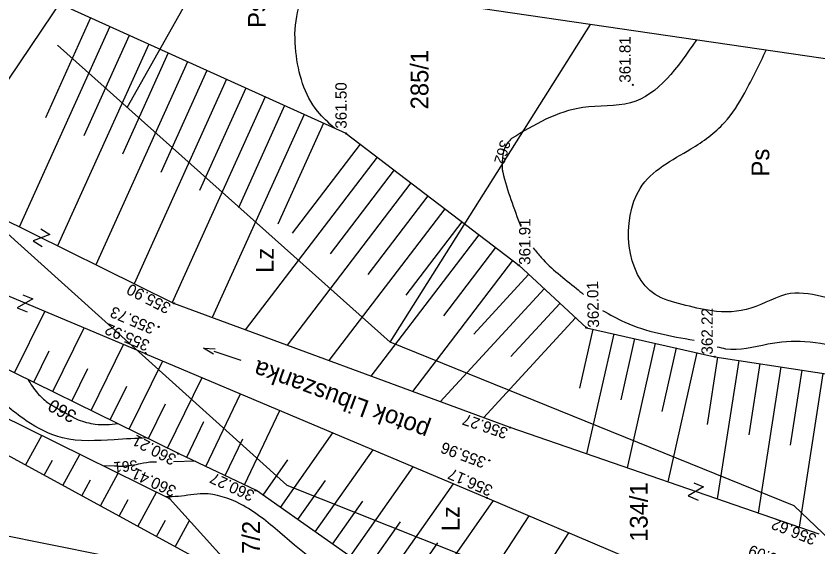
# Model space of a CAD drawing. Extents: x 4635329 to 4651863, y 5356628 to 5367582.
# Drawn here: x 4651136.6 to 4651193.1, y 5356715.5 to 5356752.8 of the extents above; entities that cross this region are included whole.
import ezdxf

# ---------------------------------------------------------------- set-up
doc = ezdxf.new("R2010")
doc.units = 0
for name, color, linetype in [('Level 1', 7, 'Continuous'), ('Level 12', 7, 'Continuous'), ('Level 4', 7, 'Continuous'), ('Level 44', 7, 'Continuous'), ('Level 45', 7, 'Continuous'), ('Level 46', 7, 'Continuous'), ('Level 47', 7, 'Continuous'), ('Level 48', 7, 'Continuous'), ('Level 5', 7, 'Continuous'), ('Level 50', 7, 'Continuous'), ('Level 51', 7, 'Continuous'), ('Level 53', 7, 'Continuous')]:
    doc.layers.add(name, color=color, linetype=linetype)

msp = doc.modelspace()

# ---------------------------------------------------------------- linework, layer by layer
at = {"layer": 'Level 1'}
for p, q in [((4651142.124, 5356757.357), (4651130.91, 5356740.759)), ((4651210.82, 5356747.317), (4651142.124, 5356757.357))]:
    msp.add_line(p, q, dxfattribs=at)
at = {"layer": 'Level 4'}
for p, q in [((4651144.438, 5356746.409), (4651149.95, 5356756.213)), ((4651162.95, 5356729.899), (4651177.067, 5356752.25)), ((4651162.95, 5356729.899), (4651139.533, 5356750.784)), ((4651133.66, 5356739.652), (4651155.671, 5356719.834)), ((4651191.397, 5356718.379), (4651162.95, 5356729.899)), ((4651155.671, 5356719.834), (4651189.548, 5356706.371)), ((4651208.259, 5356702.31), (4651191.397, 5356718.379)), ((4651130.975, 5356717.257), (4651177.535, 5356707.977))]:
    msp.add_line(p, q, dxfattribs=at)
at = {"layer": 'Level 44'}
for centre in [(4651180.045, 5356747.997), (4651159.865, 5356744.577), (4651172.015, 5356735.297), (4651147.735, 5356732.617), (4651146.655, 5356730.967), (4651176.775, 5356730.907), (4651145.732, 5356729.122), (4651185.825, 5356728.867), (4651171.415, 5356723.877), (4651148.045, 5356722.037), (4651169.945, 5356721.567), (4651153.475, 5356719.457), (4651147.415, 5356718.887), (4651169.765, 5356718.937)]:
    msp.add_circle(centre, 0.04, dxfattribs=at)
at = {"layer": 'Level 46'}
for p, q in [((4651143.548, 5356721.165), (4651142.743, 5356721.189)), ((4651149.228, 5356721.503), (4651147.711, 5356721.476))]:
    msp.add_line(p, q, dxfattribs=at)
for points in [[(4651159.027, 5356744.956), (4651157.839, 5356746.143), (4651156.321, 5356750.33), (4651156.382, 5356752.818), (4651156.989, 5356755.003), (4651157.028, 5356755.179)], [(4651184.527, 5356751.16), (4651179.887, 5356746.733), (4651176.521, 5356746.4), (4651171.498, 5356744.217)], [(4651204.195, 5356724.252), (4651203.361, 5356725.098), (4651200.995, 5356727.826), (4651199.873, 5356729.585), (4651196.249, 5356732.275), (4651193.641, 5356733.033), (4651191.154, 5356733.306), (4651188.364, 5356732.275), (4651185.605, 5356732.093), (4651183.512, 5356732.548), (4651181.615, 5356733.242), (4651180.554, 5356740.7), (4651184.132, 5356743.489), (4651186.498, 5356745.338), (4651187.923, 5356747.43), (4651189.44, 5356750.442)], [(4651171.498, 5356744.217), (4651171.224, 5356743.914), (4651170.834, 5356742.096)], [(4651170.834, 5356742.096), (4651170.89, 5356741.853), (4651172.151, 5356738.034)], [(4651173.04, 5356736.531), (4651173.589, 5356735.85), (4651176.076, 5356733.667), (4651176.575, 5356733.245)], [(4651177.917, 5356732.125), (4651179.472, 5356731.302), (4651184.374, 5356730.029)], [(4651185.981, 5356729.569), (4651186.583, 5356729.429), (4651189.555, 5356729.762), (4651192.163, 5356729.944), (4651195.087, 5356729.339), (4651196.815, 5356728.581), (4651198.605, 5356727.096), (4651198.829, 5356726.859)], [(4651145.844, 5356723.147), (4651143.522, 5356723.027), (4651139.883, 5356723.148), (4651137.335, 5356724.361), (4651134.727, 5356726.726), (4651133.575, 5356728.423), (4651132.919, 5356729.492)], [(4651137.437, 5356727.274), (4651138.124, 5356726.301), (4651138.83, 5356725.636)], [(4651138.83, 5356725.636), (4651139.883, 5356725.028), (4651140.991, 5356724.421)], [(4651140.991, 5356724.421), (4651142.188, 5356724.118), (4651143.787, 5356724.157)], [(4651145.374, 5356721.327), (4651144.128, 5356721.147), (4651143.548, 5356721.165)], [(4651146.499, 5356721.455), (4651146.251, 5356721.451), (4651145.374, 5356721.327)], [(4651163.601, 5356712.367), (4651161.083, 5356712.669), (4651155.2, 5356716.489), (4651152.41, 5356718.49), (4651149.802, 5356719.218), (4651148.043, 5356719.036), (4651147.174, 5356719.006)]]:
    msp.add_spline(points, degree=3, dxfattribs=at)
at = {"layer": 'Level 48'}
for p, q in [((4651141.854, 5356752.714), (4651138.676, 5356745.681)), ((4651143.221, 5356752.097), (4651136.845, 5356737.985)), ((4651144.588, 5356751.479), (4651141.39, 5356744.4)), ((4651145.955, 5356750.862), (4651139.538, 5356736.658)), ((4651147.322, 5356750.244), (4651144.103, 5356743.119)), ((4651148.689, 5356749.626), (4651142.23, 5356735.331)), ((4651150.056, 5356749.009), (4651146.816, 5356741.838)), ((4651151.423, 5356748.391), (4651144.922, 5356734.004)), ((4651152.79, 5356747.774), (4651149.529, 5356740.557)), ((4651154.157, 5356747.156), (4651147.615, 5356732.677)), ((4651155.524, 5356746.538), (4651152.272, 5356739.341)), ((4651156.891, 5356745.921), (4651150.43, 5356731.622)), ((4651158.257, 5356745.303), (4651155.049, 5356738.202)), ((4651160.847, 5356743.827), (4651156.066, 5356737.567)), ((4651162.039, 5356742.916), (4651152.757, 5356730.763)), ((4651163.231, 5356742.006), (4651158.73, 5356736.113)), ((4651164.423, 5356741.095), (4651155.702, 5356729.676)), ((4651165.616, 5356740.185), (4651161.395, 5356734.659)), ((4651166.808, 5356739.274), (4651158.647, 5356728.59)), ((4651168, 5356738.364), (4651164.059, 5356733.205)), ((4651169.192, 5356737.453), (4651161.592, 5356727.503)), ((4651170.384, 5356736.543), (4651166.724, 5356731.751)), ((4651171.576, 5356735.632), (4651164.536, 5356726.416)), ((4651172.711, 5356734.655), (4651168.839, 5356730.456)), ((4651173.814, 5356733.638), (4651166.489, 5356725.695)), ((4651174.917, 5356732.621), (4651171.464, 5356728.877)), ((4651136.512, 5356727.728), (4651138.637, 5356732.057)), ((4651176.019, 5356731.604), (4651169.534, 5356724.572)), ((4651139.205, 5356726.406), (4651141.408, 5356730.895)), ((4651177.236, 5356730.803), (4651176.302, 5356726.66)), ((4651178.699, 5356730.473), (4651176.795, 5356722.025)), ((4651141.898, 5356725.084), (4651144.179, 5356729.733)), ((4651180.162, 5356730.143), (4651179.192, 5356725.839)), ((4651181.625, 5356729.814), (4651179.648, 5356721.043)), ((4651137.858, 5356727.067), (4651138.94, 5356729.272)), ((4651183.089, 5356729.484), (4651182.082, 5356725.018)), ((4651184.552, 5356729.154), (4651182.502, 5356720.061)), ((4651144.591, 5356723.762), (4651146.95, 5356728.568)), ((4651186.018, 5356728.837), (4651185.286, 5356724.096)), ((4651187.5, 5356728.608), (4651185.995, 5356718.859)), ((4651140.551, 5356725.745), (4651141.672, 5356728.03)), ((4651188.983, 5356728.379), (4651188.209, 5356723.371)), ((4651190.465, 5356728.151), (4651188.877, 5356717.866)), ((4651191.948, 5356727.922), (4651191.133, 5356722.646)), ((4651147.283, 5356722.44), (4651149.718, 5356727.399)), ((4651193.43, 5356727.693), (4651191.76, 5356716.874)), ((4651143.244, 5356724.423), (4651144.405, 5356726.787)), ((4651149.988, 5356721.142), (4651152.419, 5356726.259)), ((4651145.937, 5356723.101), (4651147.135, 5356725.542)), ((4651152.698, 5356719.855), (4651155.186, 5356725.091)), ((4651148.633, 5356721.786), (4651149.835, 5356724.314)), ((4651155.23, 5356718.263), (4651158.927, 5356723.512)), ((4651137.285, 5356721.239), (4651138.42, 5356723.32)), ((4651151.343, 5356720.499), (4651152.573, 5356723.087)), ((4651157.682, 5356716.536), (4651161.755, 5356722.318)), ((4651139.918, 5356719.802), (4651141.113, 5356721.992)), ((4651138.601, 5356720.521), (4651139.184, 5356721.588)), ((4651154.004, 5356719.127), (4651155.758, 5356721.618)), ((4651142.551, 5356718.365), (4651143.806, 5356720.665)), ((4651160.135, 5356714.808), (4651164.584, 5356721.124)), ((4651141.235, 5356719.084), (4651141.847, 5356720.206)), ((4651156.456, 5356717.399), (4651158.399, 5356720.157)), ((4651162.588, 5356713.08), (4651167.412, 5356719.93)), ((4651145.185, 5356716.928), (4651146.5, 5356719.338)), ((4651143.868, 5356717.647), (4651144.511, 5356718.824)), ((4651158.909, 5356715.672), (4651161.039, 5356718.696)), ((4651165.04, 5356711.353), (4651170.24, 5356718.735)), ((4651146.501, 5356716.21), (4651147.129, 5356717.36)), ((4651147.818, 5356715.491), (4651148.822, 5356717.331)), ((4651161.361, 5356713.944), (4651163.68, 5356717.236)), ((4651167.549, 5356709.708), (4651172.743, 5356717.671)), ((4651170.062, 5356708.069), (4651175.548, 5356716.48)), ((4651163.814, 5356712.217), (4651166.32, 5356715.775))]:
    msp.add_line(p, q, dxfattribs=at)
for points in [[(4651159.865, 5356744.577), (4651140.487, 5356753.332)], [(4651159.865, 5356744.577), (4651172.015, 5356735.297), (4651176.775, 5356730.907), (4651185.825, 5356728.867), (4651199.945, 5356726.687), (4651204.495, 5356722.447), (4651214.585, 5356716.447), (4651220.475, 5356711.587), (4651225.965, 5356710.777), (4651235.295, 5356710.407), (4651240.045, 5356721.267)], [(4651181.945, 5356698.957), (4651174.695, 5356705.047), (4651165.205, 5356711.237), (4651153.535, 5356719.457), (4651148.105, 5356722.037), (4651132.135, 5356729.877)], [(4651129.435, 5356727.747), (4651147.415, 5356718.887), (4651153.085, 5356712.617)], [(4651153.085, 5356712.617), (4651128.035, 5356726.287)]]:
    msp.add_lwpolyline(points, dxfattribs=at)
at = {"layer": 'Level 50'}
for p, q in [((4651147.735, 5356732.617), (4651134.798, 5356738.994)), ((4651145.685, 5356729.101), (4651133.346, 5356734.276)), ((4651171.415, 5356723.877), (4651147.735, 5356732.617)), ((4651145.685, 5356729.101), (4651169.765, 5356718.937)), ((4651150.508, 5356729.036), (4651149.81, 5356729.476)), ((4651149.81, 5356729.476), (4651150.633, 5356729.416)), ((4651152.47, 5356728.601), (4651150.57, 5356729.226)), ((4651193.175, 5356716.387), (4651171.415, 5356723.877)), ((4651169.765, 5356718.937), (4651190.495, 5356710.127))]:
    msp.add_line(p, q, dxfattribs=at)
at = {"layer": 'Level 53'}
for p, q in [((4651138.355, 5356737.859), (4651138.987, 5356737.456)), ((4651138.987, 5356737.456), (4651137.817, 5356737.016)), ((4651137.817, 5356737.016), (4651138.45, 5356736.612)), ((4651137.097, 5356733.228), (4651137.786, 5356732.932)), ((4651137.786, 5356732.932), (4651136.703, 5356732.308)), ((4651136.703, 5356732.308), (4651137.392, 5356732.013)), ((4651185.027, 5356719.706), (4651183.954, 5356719.066)), ((4651184.334, 5356719.991), (4651185.027, 5356719.706)), ((4651183.954, 5356719.066), (4651184.647, 5356718.781))]:
    msp.add_line(p, q, dxfattribs=at)

# ---------------------------------------------------------------- texts
at = {"layer": 'Level 12'}
for s, p in [('Ps', (4651154.194, 5356752.007)), ('Ps', (4651189.654, 5356741.551)), ('Lz', (4651154.754, 5356734.76)), ('Lz', (4651167.846, 5356716.584))]:
    msp.add_text(s, height=1.25, rotation=90, dxfattribs=at).set_placement(p)
at = {"layer": 'Level 45'}
for s, rotation, p in [('361.81', 90, (4651179.895, 5356748.147)), ('361.50', 90, (4651159.896, 5356744.909)), ('361.91', 90, (4651172.834, 5356735.326)), ('362.01', 91.3333, (4651177.674, 5356730.919)), ('355.90', 152.9225, (4651147.592, 5356732.551)), ('355.73', 156.9868, (4651146.478, 5356731.151)), ('362.22', 90, (4651185.675, 5356729.017)), ('355.92', 156.9868, (4651146.099, 5356729.956)), ('356.27', 161.0996, (4651171.323, 5356723.804)), ('360.21', 152.4904, (4651147.976, 5356721.889)), ('355.96', 159.4974, (4651169.778, 5356721.74)), ('360.41', 154.9042, (4651147.974, 5356719.686)), ('360.27', 155.0784, (4651153.481, 5356719.374)), ('356.17', 156.5308, (4651170.256, 5356719.74)), ('356.62', 158.2961, (4651193.05, 5356716.312)), ('356.09', 160.3721, (4651191.451, 5356714.543))]:
    msp.add_text(s, height=0.8, rotation=rotation, dxfattribs=at).set_placement(p)
at = {"layer": 'Level 47'}
for s, height, rotation, p in [('362', 0.75, 253.2061, (4651170.747, 5356744.176)), ('360', 0.9, 150.6787, (4651140.955, 5356724.942)), ('361', 0.75, 185.5847, (4651145.135, 5356721.602))]:
    msp.add_text(s, height=height, rotation=rotation, dxfattribs=at).set_placement(p)
at = {"layer": 'Level 5'}
for s, p in [('285/1', (4651165.649, 5356746.272)), ('134/1', (4651181.09, 5356715.842)), ('387/2', (4651153.783, 5356713.124))]:
    msp.add_text(s, height=1.25, rotation=90, dxfattribs=at).set_placement(p)
at = {"layer": 'Level 51'}
msp.add_text('potok Libuszanka', height=1.25, rotation=159.7415, dxfattribs=at).set_placement((4651165.841, 5356724.144))

doc.saveas('drawing.dxf')
